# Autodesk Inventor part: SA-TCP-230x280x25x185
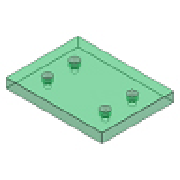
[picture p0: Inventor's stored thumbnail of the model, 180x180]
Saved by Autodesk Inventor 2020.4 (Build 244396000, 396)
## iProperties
Created: 2019-01
Part Number: SA-TCP-230x280x25x185
Material: S 55 C
Description: Top Clamping Plate
Document SubType Name: Modeling
Designer: mel
Standard Revision: 1
Manufacturer: FUTABA
Language: fr-FR
Size Designation: 230x280x25x185
Categories: <MemberInstance><Categories><Category DisplayName="Moule" InternalName="349578f2-f4d4-4954-8c09-8e99297a61c0" Mnemonic="MOLD"><Category DisplayName="Plaque de m
Density: 7.85 g/cm^3
Appearance: Clear - Green 1
IsCustomPart: 1
Author: mel
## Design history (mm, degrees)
sketch "Sketch1"
  geometry: L1 (-140, 115)-(140, 115); L2 (140, 115)-(140, -115); L3 (140, -115)-(-140, -115); L4 (-140, -115)-(-140, 115); 3 further points
  constraints: 8 end point, 2 midpoint, 2 parallel, 1 horizontal, 1 horizontal alignment, 1 perpendicular, 1 vertical alignment
  dimensions: "d72" = 280 distance between parallel lines of L2 L4 (= W_); "d73" = 230 distance between parallel lines of L3 L1 (= L)
extrude "Extrusion1" new body sketch "Sketch1" distance "d20" = 25 (= H_); taper "d30" = 0 deg
sketch "Sketch2"
  geometry: 2 further points
  dimensions: "d53" = 92.5 horizontal distance of point (0, 0) point (-92.5, 53) (= 0.5 x S1_W); "d54" = 53 vertical distance of point (0, 0) point (-92.5, 53) (= 0.5 x S1_L)
hole "Hole1" sketch "Sketch2" at (-92.5, 53) diameter "d55" = 14 (= S1_d1); stored, may be unused: countersink angle "d59" = 90 deg, drill point angle "d61" = 0 deg; dims "d56" = 6, "d57" = 20 (= S1_d2), "d58" = 13 (= S1_k), "d60" = 25 (= H_)
pattern_linear "Rectangular Pattern1" dims "d64" = 106 (computed from S1_L, Ns), "d67" = 185 (computed from S1_W, Nw)
chamfer "Chamfer1" distance "d68" = 0.5; stored, may be unused: second distance "d69" = 2, angle "d71" = 45 deg
feature "Sculpter2"
feature "Sculpter3"
body "Solid1"
feature "Surface2"
body "Srf2"
feature "Surface3"
body "Srf3"
other parameters: "L" = 230 [user parameter; used in 1 equation term], "W_" = 280 [user parameter; used in 1 equation term], "H_" = 25 [user parameter; used in 2 equation terms], "S1_W" = 185 [user parameter; used in 2 equation terms], "S1_d1" = 14 [user parameter; used in 1 equation term], "S1_d2" = 20 [user parameter; used in 1 equation term], "S1_k" = 13 [user parameter; used in 1 equation term], "S1_L" = 106 [user parameter; used in 2 equation terms]
